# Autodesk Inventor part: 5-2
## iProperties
Author: Administrator
Created: 2001-02
Part Number: 5-2
Document SubType Name: Modeling
Designer: Administrator
Control State: 0
Master: False
Checked Out: False
PropertySet Name: Design Tracking Control
Shininess: 20.0
PropertySet Name: _Private Model Information
Density: 0.0
Volumn: 0.0
Area: 0.0
PropertySet Name: Model Information
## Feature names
1. Extrusion1
2. Extrusion2
3. Hole1
4. Hole2
5. Hole3
6. Extrusion3
